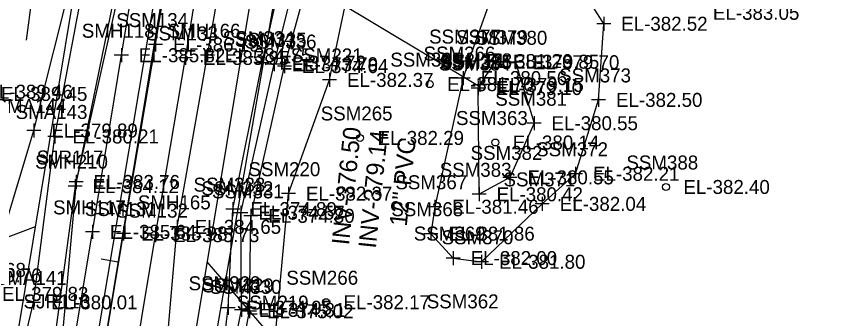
# Model space of a CAD drawing. Extents: x 1189978 to 1314812, y 571533 to 629339.
# Drawn here: x 1217523.8 to 1217758.6, y 621514.1 to 621600.5 of the extents above; entities that cross this region are included whole.
import ezdxf

# ---------------------------------------------------------------- set-up
doc = ezdxf.new("R2010")
doc.units = 0
for name, color, linetype in [('SURVEY - CENTERLINE - Preliminary', 7, 'Continuous'), ('SURVEY - CENTERLINE - Preliminary Text', 7, 'Continuous'), ('SURVEY - DRAINAGE - Area Shapes', 7, 'Continuous'), ('SURVEY - DRAINAGE - Bridge Hydraulic Data with Text', 7, 'Continuous'), ('SURVEY - DRAINAGE - Pipes and Culverts', 7, 'Continuous'), ('SURVEY - DRAINAGE - Pipes and Culverts - Points - Locators', 7, 'Continuous'), ('SURVEY - DRAINAGE - Pipes and Culverts - Points - Numbers', 7, 'Continuous'), ('SURVEY - DRAINAGE - Pipes and Culverts Text', 7, 'Continuous'), ('SURVEY - DTM - Breaklines', 7, 'Continuous'), ('SURVEY - DTM - Breaklines - Points - Elevations', 7, 'Continuous'), ('SURVEY - DTM - Breaklines - Points - Locators', 7, 'Continuous'), ('SURVEY - DTM - Breaklines - Points - Numbers', 7, 'Continuous'), ('SURVEY - DTM - Spot Points - Elevations', 7, 'Continuous'), ('SURVEY - DTM - Spot Points - Locators', 7, 'Continuous'), ('SURVEY - DTM - Spot Points - Point Numbers', 7, 'Continuous'), ('SURVEY - PROPERTY - ROW Lines', 7, 'Continuous'), ('SURVEY - PROPERTY - ROW Lines Text', 7, 'Continuous'), ('SURVEY - TRANSPORTATION - Roads', 7, 'Continuous'), ('SURVEY - TRANSPORTATION - Roads - Points - Elevations', 7, 'Continuous'), ('SURVEY - TRANSPORTATION - Roads - Points - Locators', 7, 'Continuous'), ('SURVEY - TRANSPORTATION - Roads - Points - Numbers', 7, 'Continuous'), ('SURVEY - UTILITIES - Electric (Overhead) with Text', 7, 'Continuous'), ('SURVEY - VEGETATION - Features - Points - Elevations', 7, 'Continuous'), ('SURVEY - VEGETATION - Features - Points - Locators', 7, 'Continuous'), ('SURVEY - VEGETATION - Features - Points - Numbers', 7, 'Continuous'), ('SURVEY - VEGETATION - Features with Text', 7, 'Continuous')]:
    doc.layers.add(name, color=color, linetype=linetype)

msp = doc.modelspace()

# ---------------------------------------------------------------- linework, layer by layer
at = {"layer": 'SURVEY - CENTERLINE - Preliminary'}
msp.add_line((1217525.37, 621363.65), (1217649.69, 622116.55), dxfattribs=at)
msp.add_line((1217525.37, 621363.65), (1217649.69, 622116.55), dxfattribs=at)
at = {"layer": 'SURVEY - CENTERLINE - Preliminary Text'}
msp.add_line((1217552.87, 621530.2), (1217547.94, 621531.02), dxfattribs=at)
at = {"layer": 'SURVEY - DRAINAGE - Area Shapes'}
msp.add_line((1217415.87, 620731.68), (1218149.36, 625079.9), dxfattribs=at)
at = {"layer": 'SURVEY - DRAINAGE - Bridge Hydraulic Data with Text'}
for p, q in [((1217526.67, 621593.65), (1217529.41, 621614.48)), ((1217578.32, 621591.37), (1217578.32, 621587.37)), ((1217580.32, 621589.37), (1217576.32, 621589.37)), ((1217613.22, 621584.3), (1217613.22, 621580.3)), ((1217615.22, 621582.3), (1217611.22, 621582.3)), ((1217603.47, 621549.78), (1217599.47, 621549.78)), ((1217601.47, 621551.78), (1217601.47, 621547.78)), ((1217571.7, 621540.29), (1217567.7, 621540.29)), ((1217569.7, 621542.29), (1217569.7, 621538.29))]:
    msp.add_line(p, q, dxfattribs=at)
for points in [[(1217505.54, 621026.79), (1217510.58, 621028.06), (1217516.48, 621028.53), (1217518.24, 621034.42), (1217525.77, 621071.02), (1217531.12, 621100.75), (1217543.76, 621178.47), (1217557.61, 621268.24), (1217565, 621315.17), (1217570.43, 621349.89), (1217572.63, 621390.62), (1217580.88, 621434.75), (1217592.39, 621481.3), (1217594.39, 621494.68), (1217597.98, 621511.62), (1217601.47, 621549.78), (1217613.22, 621582.3), (1217623.08, 621629.44), (1217625.8, 621646.39), (1217625.26, 621664.85), (1217620.87, 621681.67)], [(1217505.54, 621026.79), (1217497.33, 621030.97), (1217494.44, 621038.22), (1217497.2, 621080.45), (1217509.01, 621144.38), (1217516.68, 621191.71), (1217524.09, 621241.49), (1217533.15, 621294.15), (1217540.61, 621345.97), (1217548.02, 621393.69), (1217553.92, 621442.08), (1217565.44, 621490.61), (1217569.7, 621540.29), (1217578.32, 621589.37), (1217586.92, 621638.9), (1217590.67, 621661.55), (1217589.09, 621673.95), (1217587.38, 621675.54)]]:
    msp.add_lwpolyline(points, dxfattribs=at)
at = {"layer": 'SURVEY - DRAINAGE - Pipes and Culverts'}
msp.add_line((1217655.99, 621580.4), (1217606.77, 621609.94), dxfattribs=at)
at = {"layer": 'SURVEY - DRAINAGE - Pipes and Culverts - Points - Locators'}
for p, q in [((1217656.24, 621580.4), (1217655.74, 621580.4)), ((1217655.99, 621580.15), (1217655.99, 621580.65)), ((1217655.99, 621580.4), (1217655.99, 621580.4)), ((1217655.99, 621580.4), (1217655.99, 621580.4))]:
    msp.add_line(p, q, dxfattribs=at)
at = {"layer": 'SURVEY - DTM - Breaklines'}
for points in [[(1217387.16, 620695.14), (1217397.48, 620747.65), (1217407.02, 620809.24), (1217418.75, 620878.96), (1217427.19, 620935.15), (1217426.68, 620940.89), (1217441.48, 620996.6), (1217449.24, 621046.98), (1217458, 621101.08), (1217460.79, 621140.2), (1217471.39, 621192.44), (1217489.7, 621292.1), (1217492.93, 621335.46), (1217504.86, 621384.61), (1217513.97, 621433.22), (1217517.91, 621473.83), (1217528.68, 621518.7), (1217534.78, 621566.14), (1217543.47, 621612.64), (1217549.89, 621643.65), (1217551.17, 621685.8), (1217565.36, 621705.38)], [(1217504.64, 621476.68), (1217514.65, 621521.12), (1217528.76, 621567.82), (1217540.11, 621613.1), (1217546.43, 621644.25), (1217544.27, 621681.39), (1217509.23, 621703.06)], [(1217510.22, 621032.47), (1217510.67, 621035.51), (1217516.56, 621076.89), (1217522.63, 621118.37), (1217524.37, 621130.68), (1217531.06, 621153.32), (1217534.84, 621195.27), (1217541.13, 621235.58), (1217547.86, 621274.25), (1217552.16, 621315.03), (1217559.39, 621352.71), (1217565.05, 621392.35), (1217570.59, 621431.17), (1217579.74, 621465.58), (1217585.39, 621503.25), (1217588.03, 621516.54), (1217587.87, 621544.34), (1217597.4, 621586.78), (1217605.23, 621618.41), (1217611.84, 621655.72), (1217609.15, 621679.37), (1217607.18, 621692.62), (1217600.47, 621698.35)], [(1217510.22, 621032.47), (1217512.12, 621031.07), (1217514.39, 621035.67), (1217519.35, 621076.45), (1217525.78, 621118.11), (1217527.24, 621129.57), (1217533.8, 621152.91), (1217537.06, 621194.25), (1217544.11, 621234.91), (1217551.92, 621273.85), (1217555.69, 621314.91), (1217562.5, 621351.44), (1217567.38, 621391.58), (1217573.29, 621430.4), (1217583.03, 621465.15), (1217587.76, 621502.7), (1217590.39, 621516.14), (1217590.71, 621543.44), (1217600.32, 621586.27), (1217609.15, 621618.28), (1217615.53, 621654.98), (1217611.84, 621679.95), (1217608.98, 621694.45), (1217608.75, 621696.58)], [(1217510.58, 621028.06), (1217508.12, 621030.69), (1217507.01, 621036.89), (1217513.63, 621077.21), (1217519.37, 621118.67), (1217522.53, 621131.01), (1217528.61, 621154.7), (1217531.08, 621195.41), (1217537.78, 621236.3), (1217543.58, 621274.68), (1217548.51, 621316.14), (1217556.97, 621353.31), (1217561.88, 621392.99), (1217568.36, 621432.01), (1217577.69, 621466.22), (1217582.73, 621504.23), (1217584.25, 621517.15), (1217585.6, 621545.35), (1217593.93, 621587.24), (1217602.31, 621624.58), (1217607.97, 621656.51), (1217606.79, 621679.18), (1217604.88, 621690.79), (1217551.17, 621685.8)], [(1217418.06, 620739.44), (1217427.36, 620792.56), (1217436.72, 620845.05), (1217446.22, 620900.31), (1217455.61, 620954.21), (1217464.26, 621004.54), (1217473.29, 621056.89), (1217481.83, 621108.05), (1217491.34, 621163.83), (1217500.43, 621216.55), (1217508.98, 621267.02), (1217518.36, 621323.37), (1217527.29, 621375.81), (1217536.19, 621428.97), (1217544.91, 621481.66), (1217554.38, 621538.38), (1217563.54, 621592.41), (1217571.82, 621642.48), (1217577.37, 621677.13)], [(1217567.58, 621678.78), (1217566.65, 621676.81), (1217561.06, 621675.09), (1217559.37, 621666.41), (1217560.08, 621650.79), (1217551.98, 621602.78), (1217540.51, 621551.93), (1217533.57, 621500.33), (1217524.41, 621453.51), (1217516.18, 621399.79), (1217505.66, 621346.61), (1217497.91, 621291.92), (1217486.51, 621241.58), (1217479.66, 621189.93), (1217471.35, 621146.03), (1217465.62, 621095.91), (1217456.92, 621043.82), (1217448.31, 620989.84), (1217436.81, 620938.63)], [(1217652.9, 621587.7), (1217651.43, 621582.83), (1217643.26, 621546.04), (1217642.15, 621538.34), (1217648.55, 621531.36), (1217656.64, 621530.3), (1217674, 621546.86), (1217683.49, 621555.46), (1217690.06, 621576.59), (1217691.54, 621598.37), (1217679.54, 621617.42), (1217663.26, 621616.86), (1217652.9, 621587.7)], [(1217655.69, 621579.99), (1217656.16, 621580.89), (1217660.59, 621587.52), (1217666.32, 621587.36), (1217671.64, 621569.93), (1217664.75, 621554.44), (1217655.93, 621549.6), (1217655.69, 621579.99)]]:
    msp.add_lwpolyline(points, dxfattribs=at)
at = {"layer": 'SURVEY - DTM - Breaklines - Points - Locators'}
for p, q in [((1217691.54, 621600.37), (1217691.54, 621596.37)), ((1217693.54, 621598.37), (1217689.54, 621598.37)), ((1217563.54, 621594.41), (1217563.54, 621590.41)), ((1217565.54, 621592.41), (1217561.54, 621592.41)), ((1217652.9, 621589.7), (1217652.9, 621585.7)), ((1217595.93, 621587.24), (1217591.93, 621587.24)), ((1217593.93, 621589.24), (1217593.93, 621585.24)), ((1217597.4, 621588.78), (1217597.4, 621584.78)), ((1217600.32, 621588.27), (1217600.32, 621584.27)), ((1217654.9, 621587.7), (1217650.9, 621587.7)), ((1217662.59, 621587.52), (1217658.59, 621587.52)), ((1217660.59, 621589.52), (1217660.59, 621585.52)), ((1217668.32, 621587.36), (1217664.32, 621587.36)), ((1217666.32, 621589.36), (1217666.32, 621585.36)), ((1217599.4, 621586.78), (1217595.4, 621586.78)), ((1217602.32, 621586.27), (1217598.32, 621586.27)), ((1217653.43, 621582.83), (1217649.43, 621582.83)), ((1217651.43, 621584.83), (1217651.43, 621580.83)), ((1217656.16, 621582.89), (1217656.16, 621578.89)), ((1217658.16, 621580.89), (1217654.16, 621580.89)), ((1217655.69, 621581.99), (1217655.69, 621577.99)), ((1217657.69, 621579.99), (1217653.69, 621579.99)), ((1217690.06, 621578.59), (1217690.06, 621574.59)), ((1217692.06, 621576.59), (1217688.06, 621576.59)), ((1217671.64, 621571.93), (1217671.64, 621567.93)), ((1217528.76, 621569.82), (1217528.76, 621565.82)), ((1217673.64, 621569.93), (1217669.64, 621569.93)), ((1217530.76, 621567.82), (1217526.76, 621567.82)), ((1217536.78, 621566.14), (1217532.78, 621566.14)), ((1217534.78, 621568.14), (1217534.78, 621564.14)), ((1217683.49, 621557.46), (1217683.49, 621553.46)), ((1217666.75, 621554.44), (1217662.75, 621554.44)), ((1217664.75, 621556.44), (1217664.75, 621552.44)), ((1217685.49, 621555.46), (1217681.49, 621555.46)), ((1217540.51, 621553.93), (1217540.51, 621549.93)), ((1217542.51, 621551.93), (1217538.51, 621551.93)), ((1217655.93, 621551.6), (1217655.93, 621547.6)), ((1217585.6, 621547.35), (1217585.6, 621543.35)), ((1217643.26, 621548.04), (1217643.26, 621544.04)), ((1217657.93, 621549.6), (1217653.93, 621549.6)), ((1217674, 621548.86), (1217674, 621544.86)), ((1217587.6, 621545.35), (1217583.6, 621545.35)), ((1217587.87, 621546.34), (1217587.87, 621542.34)), ((1217590.71, 621545.44), (1217590.71, 621541.44)), ((1217645.26, 621546.04), (1217641.26, 621546.04)), ((1217676, 621546.86), (1217672, 621546.86)), ((1217589.87, 621544.34), (1217585.87, 621544.34)), ((1217592.71, 621543.44), (1217588.71, 621543.44)), ((1217554.38, 621540.38), (1217554.38, 621536.38)), ((1217642.15, 621540.34), (1217642.15, 621536.34)), ((1217556.38, 621538.38), (1217552.38, 621538.38)), ((1217644.15, 621538.34), (1217640.15, 621538.34)), ((1217648.55, 621533.36), (1217648.55, 621529.36)), ((1217650.55, 621531.36), (1217646.55, 621531.36)), ((1217656.64, 621532.3), (1217656.64, 621528.3)), ((1217658.64, 621530.3), (1217654.64, 621530.3)), ((1217528.68, 621520.7), (1217528.68, 621516.7)), ((1217584.25, 621519.15), (1217584.25, 621515.15)), ((1217530.68, 621518.7), (1217526.68, 621518.7)), ((1217586.25, 621517.15), (1217582.25, 621517.15)), ((1217588.03, 621518.54), (1217588.03, 621514.54)), ((1217590.39, 621518.14), (1217590.39, 621514.14)), ((1217590.03, 621516.54), (1217586.03, 621516.54)), ((1217592.39, 621516.14), (1217588.39, 621516.14))]:
    msp.add_line(p, q, dxfattribs=at)
at = {"layer": 'SURVEY - DTM - Spot Points - Locators'}
for centre in [(1217641.82, 621581.1), (1217621.94, 621565.71), (1217660.58, 621564.41), (1217709.31, 621551.69), (1217612.22, 621518.74)]:
    msp.add_circle(centre, 1, dxfattribs=at)
at = {"layer": 'SURVEY - PROPERTY - ROW Lines'}
for p, q in [((1217500.7, 621367.73), (1217557.72, 621713)), ((1217606.4, 621700.95), (1217550.03, 621359.58))]:
    msp.add_line(p, q, dxfattribs=at)
at = {"layer": 'SURVEY - PROPERTY - ROW Lines Text'}
for points in [[(1217457.41, 621513.25), (1217529.21, 621540.36)], [(1217612.59, 621490.46), (1217578.22, 621530.27)]]:
    msp.add_lwpolyline(points, dxfattribs=at)
at = {"layer": 'SURVEY - TRANSPORTATION - Roads'}
for points in [[(1217409.51, 620742.51), (1217418.87, 620794.59), (1217428.1, 620847.79), (1217437.4, 620901.38), (1217446.45, 620953.25), (1217455.44, 621005.6), (1217463.89, 621055.84), (1217472.9, 621108.56), (1217482.31, 621162.33), (1217491.19, 621215.01), (1217500.52, 621270.57), (1217509.55, 621324.4), (1217518.06, 621374.09), (1217518.81, 621378.64), (1217527.27, 621430.43), (1217535.85, 621480.99), (1217545.48, 621538.85), (1217553.74, 621589.36), (1217562.47, 621641.97), (1217568.75, 621678.54), (1217567.58, 621678.78)], [(1217427.25, 620738.21), (1217436.59, 620791.34), (1217445.34, 620842.59), (1217455.15, 620898.88), (1217464.25, 620950.62), (1217473.39, 621002.58), (1217480.67, 621046.8), (1217490.83, 621106.73), (1217500.22, 621160.55), (1217509.53, 621215.72), (1217518.41, 621266.5), (1217527.5, 621321.85), (1217536.34, 621374.24), (1217563.48, 621537.92), (1217572.05, 621588.6), (1217580.58, 621640.89), (1217586, 621675.75), (1217587.38, 621675.54)]]:
    msp.add_lwpolyline(points, dxfattribs=at)
at = {"layer": 'SURVEY - TRANSPORTATION - Roads - Points - Locators'}
for p, q in [((1217553.74, 621591.36), (1217553.74, 621587.36)), ((1217572.05, 621590.6), (1217572.05, 621586.6)), ((1217555.74, 621589.36), (1217551.74, 621589.36)), ((1217574.05, 621588.6), (1217570.05, 621588.6)), ((1217545.48, 621540.85), (1217545.48, 621536.85)), ((1217547.48, 621538.85), (1217543.48, 621538.85)), ((1217565.48, 621537.92), (1217561.48, 621537.92)), ((1217563.48, 621539.92), (1217563.48, 621535.92))]:
    msp.add_line(p, q, dxfattribs=at)
at = {"layer": 'SURVEY - UTILITIES - Electric (Overhead) with Text'}
msp.add_lwpolyline([(1217806.14, 622777), (1217743.09, 622422.64), (1217688.2, 622113.29), (1217626.83, 621775.19), (1217569.14, 621442.23), (1217508.83, 621100.02), (1217448.24, 620751.9)], dxfattribs=at)
at = {"layer": 'SURVEY - VEGETATION - Features - Points - Locators'}
for p, q in [((1217540.8, 621555.12), (1217540.8, 621551.12)), ((1217542.8, 621553.12), (1217538.8, 621553.12))]:
    msp.add_line(p, q, dxfattribs=at)
at = {"layer": 'SURVEY - VEGETATION - Features with Text'}
msp.add_lwpolyline([(1217560.76, 621675.93), (1217556.7, 621644.18), (1217551.37, 621604.87), (1217540.8, 621553.12), (1217537.15, 621511.96), (1217530.13, 621471.54), (1217522.44, 621431.38), (1217515.9, 621389.36), (1217510.94, 621348.81), (1217502.94, 621307.06), (1217494.55, 621266.12), (1217486.37, 621220.88), (1217482.4, 621178.78), (1217475.75, 621141.85), (1217465.35, 621099.73), (1217457.55, 621059.45), (1217452.15, 621021.57), (1217443.78, 620977.07), (1217434.58, 620932.47)], dxfattribs=at)

# ---------------------------------------------------------------- texts
at = {"layer": 'SURVEY - DRAINAGE - Pipes and Culverts - Points - Numbers'}
msp.add_text('SSM385', height=4, dxfattribs=at).set_placement((1217644.75, 621585.4))
at = {"layer": 'SURVEY - DRAINAGE - Pipes and Culverts Text'}
for s, p in [('INV-376.50', (1217618.76, 621534.93)), ('INV-379.14', (1217626.44, 621533.97)), ('12" PVC', (1217635.26, 621540.28))]:
    msp.add_text(s, height=5, rotation=84.1019, dxfattribs=at).set_placement(p)
at = {"layer": 'SURVEY - DTM - Breaklines - Points - Elevations'}
for s, p in [('EL-382.52', (1217696.54, 621596.37)), ('EL-386.19', (1217568.54, 621590.41)), ('EL-384.75', (1217583.32, 621587.37)), ('EL-381.26', (1217657.9, 621585.7)), ('EL-379.85', (1217665.59, 621585.52)), ('EL-374.72', (1217598.93, 621585.24)), ('EL-373.79', (1217602.4, 621584.78)), ('EL-374.64', (1217605.32, 621584.27)), ('EL-379.70', (1217671.32, 621585.36)), ('EL-380.56', (1217656.43, 621580.83)), ('EL-382.37', (1217618.22, 621580.3)), ('EL-379.15', (1217661.16, 621578.89)), ('EL-389.46', (1217515.18, 621576.93)), ('EL-389.45', (1217519.35, 621576.31)), ('EL-379.10', (1217660.69, 621577.99)), ('EL-382.50', (1217695.06, 621574.59)), ('EL-380.55', (1217676.64, 621567.93)), ('EL-379.89', (1217533.76, 621565.82)), ('EL-380.21', (1217539.78, 621564.14)), ('EL-382.21', (1217688.49, 621553.46)), ('EL-380.55', (1217669.75, 621552.44)), ('EL-384.12', (1217545.51, 621549.93)), ('EL-382.37', (1217606.47, 621547.78)), ('EL-380.42', (1217660.93, 621547.6)), ('EL-374.89', (1217590.6, 621543.35)), ('EL-381.46', (1217648.26, 621544.04)), ('EL-382.04', (1217679, 621544.86)), ('EL-374.57', (1217592.87, 621542.34)), ('EL-374.80', (1217595.71, 621541.44)), ('EL-385.98', (1217559.38, 621536.38)), ('EL-384.65', (1217574.7, 621538.29)), ('EL-381.86', (1217647.15, 621536.34)), ('EL-382.00', (1217653.55, 621529.36)), ('EL-381.80', (1217661.64, 621528.3)), ('EL-389.68', (1217501.79, 621525.97)), ('EL-389.76', (1217506.25, 621524.42)), ('EL-379.83', (1217519.65, 621519.12)), ('EL-380.01', (1217533.68, 621516.7)), ('EL-374.95', (1217589.25, 621515.15)), ('EL-374.81', (1217593.03, 621514.54)), ('EL-375.02', (1217595.39, 621514.14))]:
    msp.add_text(s, height=4, dxfattribs=at).set_placement(p)
at = {"layer": 'SURVEY - DTM - Breaklines - Points - Numbers'}
for s, p in [('SSM134', (1217552.3, 621597.41)), ('SMH166', (1217566.97, 621594.37)), ('SSM377', (1217641.66, 621592.7)), ('SSM334', (1217582.69, 621592.24)), ('SSM335', (1217586.16, 621591.78)), ('SSM336', (1217588.97, 621591.27)), ('SSM379', (1217649.34, 621592.52)), ('SSM380', (1217654.91, 621592.36)), ('SSM221', (1217602.14, 621587.3)), ('SSM366', (1217640.08, 621587.83)), ('SSM378', (1217644.87, 621585.89)), ('SSM384', (1217644.45, 621584.99)), ('SSM373', (1217678.82, 621581.59)), ('SSM381', (1217660.56, 621574.93)), ('SMA144', (1217517.52, 621572.82)), ('SMA143', (1217523.54, 621571.14)), ('SSM372', (1217672.25, 621560.46)), ('SSM382', (1217653.51, 621559.44)), ('SMH210', (1217529.1, 621556.93)), ('SSM220', (1217590.06, 621554.78)), ('SSM383', (1217644.69, 621554.6)), ('SSM333', (1217574.36, 621550.35)), ('SSM367', (1217632.02, 621551.04)), ('SSM371', (1217662.92, 621551.86)), ('SSM332', (1217576.63, 621549.34)), ('SSM331', (1217579.63, 621548.44)), ('SSM131', (1217543.3, 621543.38)), ('SMH165', (1217558.46, 621545.29)), ('SSM368', (1217630.87, 621543.34)), ('SSM369', (1217637.29, 621536.36)), ('SSM370', (1217645.23, 621535.3)), ('SMA141', (1217517.6, 621523.7)), ('SSM328', (1217572.96, 621522.15)), ('SSM329', (1217576.78, 621521.54)), ('SSM330', (1217578.98, 621521.14)), ('SSM219', (1217586.72, 621516.62))]:
    msp.add_text(s, height=4, dxfattribs=at).set_placement(p)
at = {"layer": 'SURVEY - DTM - Spot Points - Elevations'}
for s, p in [('EL-383.05', (1217722.75, 621599.5)), ('EL-381.70', (1217646.82, 621579.1)), ('EL-382.29', (1217626.94, 621563.71)), ('EL-380.14', (1217665.58, 621562.41)), ('EL-382.40', (1217714.31, 621549.69)), ('EL-382.17', (1217617.22, 621516.74))]:
    msp.add_text(s, height=4, dxfattribs=at).set_placement(p)
at = {"layer": 'SURVEY - DTM - Spot Points - Point Numbers'}
for s, p in [('SSM365', (1217630.58, 621586.1)), ('SSM265', (1217610.7, 621570.71)), ('SSM363', (1217649.34, 621569.41)), ('SSM388', (1217698.02, 621556.69)), ('SSM266', (1217600.87, 621523.74)), ('SSM362', (1217640.99, 621516.98))]:
    msp.add_text(s, height=4, dxfattribs=at).set_placement(p)
at = {"layer": 'SURVEY - TRANSPORTATION - Roads - Points - Elevations'}
for s, p in [('EL-385.82', (1217558.74, 621587.36)), ('EL-385.95', (1217577.05, 621586.6)), ('EL-385.64', (1217550.48, 621536.85)), ('EL-385.73', (1217568.48, 621535.92))]:
    msp.add_text(s, height=4, dxfattribs=at).set_placement(p)
at = {"layer": 'SURVEY - TRANSPORTATION - Roads - Points - Numbers'}
for s, p in [('SMH118', (1217542.45, 621594.36)), ('SSM133', (1217560.81, 621593.6)), ('SMH117', (1217534.24, 621543.85)), ('SSM132', (1217552.24, 621542.92))]:
    msp.add_text(s, height=4, dxfattribs=at).set_placement(p)
at = {"layer": 'SURVEY - VEGETATION - Features - Points - Elevations'}
msp.add_text('EL-383.76', height=4, dxfattribs=at).set_placement((1217545.8, 621551.12))
at = {"layer": 'SURVEY - VEGETATION - Features - Points - Numbers'}
for s, p in [('SJR117', (1217529.56, 621558.12)), ('SJR116', (1217525.8, 621516.96))]:
    msp.add_text(s, height=4, dxfattribs=at).set_placement(p)

doc.saveas('drawing.dxf')
